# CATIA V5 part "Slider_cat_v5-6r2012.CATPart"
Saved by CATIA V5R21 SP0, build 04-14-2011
Part number: Slider
Bounding box of the stored display mesh (mm): x -10 to 10, y -69.282 to 69.282, z -70 to 10
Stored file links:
  D:\CATIA V5R21 E-RESOURCES\CATIA-V5R21\catia-v5r21-Tut\c16-catia-v5r21-tut\c16-catia-v5r21-tut05\Slider_cat_v5r21.CATPart
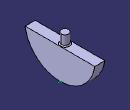
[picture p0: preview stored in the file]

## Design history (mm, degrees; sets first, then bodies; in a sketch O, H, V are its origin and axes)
Body1 (main body)
  Sketch1 on yz-plane, origin (0, 0, 0), H (0, 1, 0), V (0, 0, 1)
    arc A1 centre (0, 0) radius 70 from (-69.282, -10) to (69.282, -10) ccw
    point P1 (0, 0)
    point P2 (-69.282, -10)
    point P3 (69.282, -10)
    point P4 (0, 0)
    point P5 (-69.282, -10)
    line L1 (-69.282, -10) -> (69.282, -10)
    point P6 (69.282, -10)
    point P7 (-69.282, -10)
    reference intersected line E1 through (0, 0) direction (-1, 0) from xy-plane
    reference intersected line E3 through (0, 0) direction (0, 1) from zx-plane
    radius A1 = 70
    distance L1 P1 = 10
    coincidence: P1 V, P4 V, P6 P3, P7 A1, P2 P7, E3 P1, P2 L1, P3 L1, H P4, P2 P5, P1 H
    horizontal: L1 H, E1 H
    vertical: E3 V
    perpendicularity: E3 L1
  Pad1: profile Sketch1, direction (1, 0, 0), length 10, mirrored extent
  Point1: type OnCurve, Support edge [face of Pad1 from Sketch1.A1 | end face of Pad1], Ratio 0.5
  Sketch2 on face of Pad1 from Sketch1.L1, origin (0, 0, -10), H (1, 0, 0), V (0, 1, 0)
    circle A1 centre (0, 0) radius 7.5
    point P1 (0, 0)
    reference projected line E1 (10, 69.282) -> (10, -69.282) from edge [face of Pad1 from Sketch1.L1 | end face of Pad1]
    radius A1 = 7.5
    distance P1 E1 = 10
    coincidence: P1 H
  Pad2: profile Sketch2, direction (0, 0, 1), length 20
  Fillet1: radius 2, on edge [face of Pad1 from Sketch1.L1 | face of Pad2 from Sketch2.A1]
